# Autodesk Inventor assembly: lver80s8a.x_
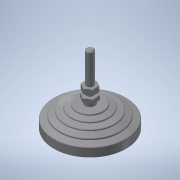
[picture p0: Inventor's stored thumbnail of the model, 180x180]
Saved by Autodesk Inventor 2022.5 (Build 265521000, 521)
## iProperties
Part Number: lver80s8a.x_
Material: 一般
Document SubType Name: Assembly
Designer: ImaoCorp
Sending System: SOLIDWORKS 2017-2017317
MC: AMD64
MC_MODEL: Intel64 Family 6 Model 60 Stepping 3, GenuineIntel
OS: Windows_NT
FRU: Parasolid Version 29.0, build 201,  4-17-2017
FORMAT: text
GUISE: transmit
KEY: lver80s8a
FILE: lver80s8a.x_t
DATE: Mon Jul 01 18:29:01 2019
Author: ImaoCorp
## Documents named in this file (3)
- X:\14_SW2022-Inv2022\00_全2023-1023新製品(TCC)まで\l\lver80s8a\LVER80S8A.iam
- X:\14_SW2022-Inv2022\00_全2023-1023新製品(TCC)まで\l\lver80s8a\lver80s8a_01.ipt
- X:\14_SW2022-Inv2022\00_全2023-1023新製品(TCC)まで\l\lver80s8a\lver80s8a_02.ipt
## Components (2 placed, 2 different names)
1. lver80s8a_01
2. lver80s8a_02
